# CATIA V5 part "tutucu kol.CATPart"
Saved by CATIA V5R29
Part number: tutucu kol
Revision: HERHANG?
Definition: B??MEYEN
Nomenclature: tutucu kol
Source: Unknown
Bounding box of the stored display mesh (mm): x -0.144 to 377, y -366.554 to 0, z 22.284 to 147.443
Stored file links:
  C:\Users\제5강의실-27\Desktop\가치같이_내작업\tutucu kol.CATPart
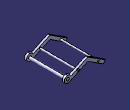
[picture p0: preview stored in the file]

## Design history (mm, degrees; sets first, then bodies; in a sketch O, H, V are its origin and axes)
Body1 "Y?seklik-Ekstr?yon1" (main body)
  Solid1: solid without history
Body2 "Y?seklik-Ekstr?yon4"
  Solid2: solid without history
Body3 "Y?seklik-Ekstr?yon5[1]"
  Solid3: solid without history
Body4 "Y?seklik-Ekstr?yon5[2]"
  Solid4: solid without history
Body5 "Y?seklik-Ekstr?yon5[3]"
  Solid5: solid without history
